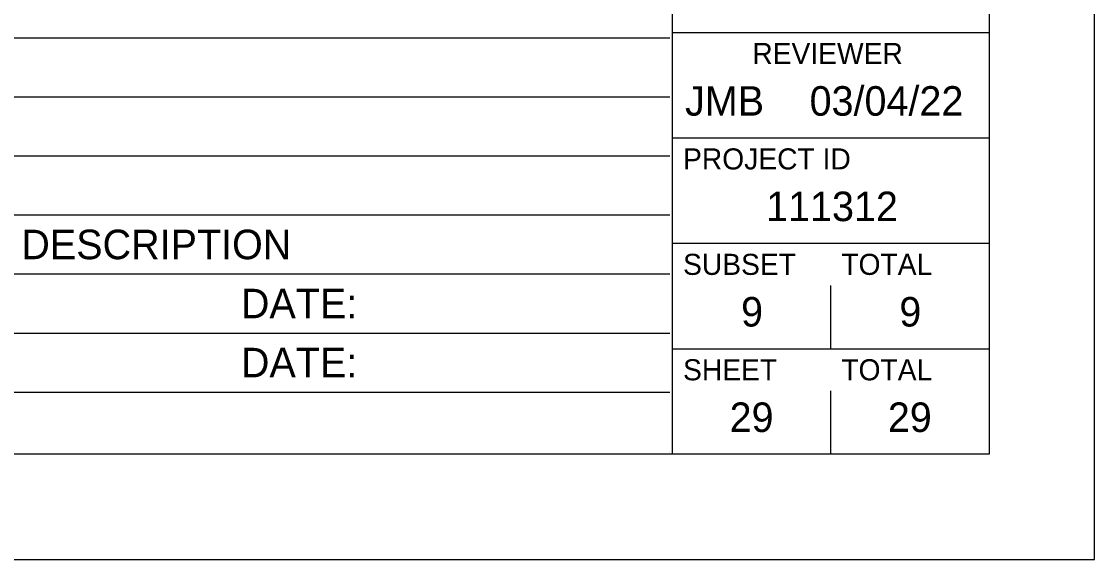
# Model space of a CAD drawing. Extents: x 0 to 88.1, y -6.1 to 35.8.
# Drawn here: x 28.91 to 34, y 0 to 2.55 of the extents above; entities that cross this region are included whole.
import ezdxf

# ---------------------------------------------------------------- set-up
doc = ezdxf.new("R2010")
doc.units = 0
for name, color, linetype in [('Default', 7, 'Continuous'), ('SH_Border', 7, 'Continuous'), ('SH_Cut_Line', 7, 'Continuous'), ('SH_Data', 7, 'Continuous'), ('SH_Text', 7, 'Continuous')]:
    doc.layers.add(name, color=color, linetype=linetype)

msp = doc.modelspace()

# ---------------------------------------------------------------- linework, layer by layer
at = {"layer": 'SH_Border'}
for p, q in [((32, 0.5), (32, 21.5)), ((32, 2.5), (33.5, 2.5)), ((32, 2), (33.5, 2)), ((32, 1.5), (33.5, 1.5)), ((32, 1), (33.5, 1))]:
    msp.add_line(p, q, dxfattribs=at)
msp.add_lwpolyline([(1.5, 21.5), (33.5, 21.5), (33.5, 0.5), (1.5, 0.5)], close=True, dxfattribs=at)
at = {"layer": 'SH_Cut_Line'}
msp.add_lwpolyline([(0, 0), (34, 0), (34, 22), (0, 22)], close=True, dxfattribs=at)
at = {"layer": 'SH_Data'}
for p, q in [((32.75, 1), (32.75, 1.3)), ((32.75, 0.5), (32.75, 0.8)), ((32.375, 0.675), (32.375, 0.675))]:
    msp.add_line(p, q, dxfattribs=at)
at = {"layer": 'SH_Text'}
for p, q in [((25.1841, 2.4744), (31.9876, 2.4744)), ((25.1841, 2.1944), (31.9876, 2.1944)), ((25.1841, 1.9144), (31.9876, 1.9144)), ((25.1841, 1.6344), (31.9876, 1.6344)), ((25.1841, 1.3544), (31.9876, 1.3544)), ((25.1841, 1.0744), (31.9876, 1.0744)), ((25.1841, 0.7944), (31.9876, 0.7944)), ((31.9876, 0.5144), (31.9876, 0.5144))]:
    msp.add_line(p, q, dxfattribs=at)

# ---------------------------------------------------------------- texts
at = {"layer": 'Default'}
for s, height, p in [('REVIEWER', 0.1, (32.3783, 2.35)), ('JMB', 0.14, (32.0596, 2.105)), ('03/04/22', 0.14, (32.6497, 2.105)), ('111312', 0.14, (32.4435, 1.605)), ('9', 0.14, (32.325, 1.105)), ('9', 0.14, (33.075, 1.105)), ('29', 0.14, (32.2706, 0.605)), ('29', 0.14, (33.0206, 0.605))]:
    msp.add_text(s, height=height, dxfattribs=at).set_placement(p)
at = {"layer": 'SH_Data'}
for s, p in [('PROJECT ID', (32.05, 1.85)), ('SUBSET', (32.05, 1.35)), ('TOTAL', (32.8, 1.35)), ('SHEET', (32.05, 0.85)), ('TOTAL', (32.8, 0.85))]:
    msp.add_text(s, height=0.1, dxfattribs=at).set_placement(p)
at = {"layer": 'SH_Text'}
for s, p in [('DESCRIPTION', (28.9143, 1.4244)), ('DATE:', (29.9549, 1.1444)), ('DATE:', (29.9549, 0.8644))]:
    msp.add_text(s, height=0.14, dxfattribs=at).set_placement(p)

doc.saveas('drawing.dxf')
